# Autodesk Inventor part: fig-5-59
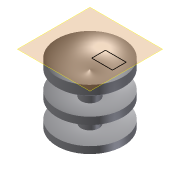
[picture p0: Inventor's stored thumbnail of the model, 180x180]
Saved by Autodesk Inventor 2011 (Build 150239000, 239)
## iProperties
Created: 2004-05
Part Number: fig-5-59
Document SubType Name: Modeling
Designer: CADCIM Technologies
Manufacturer: Standard
Standards Organization: Custom
Density: 1 g/cm^3
Author: CADCIM Technologies
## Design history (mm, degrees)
sketch "Sketch1"
  geometry: L1 (0.098, 22.743)-(0.098, 0.516); L2 (-3.621, 19.305)-(-3.621, 13.061); L3 (-3.621, 10.379)-(-3.621, 3.25); L4 (-3.664, 0.516)-(0.098, 0.516); L5 (-13.694, 4.7)-(-13.694, 1.836); L6 (-13.694, 26.851)-(-13.694, 23.014); L7 (-13.694, 15.335)-(-13.694, 12.343); A1 r 10.546 centre (-4.597, 32.185) between (-13.694, 26.851) and (0.098, 22.743); A2 r 21.828 centre (-4.597, 32.185) between (-13.694, 12.343) and (-3.621, 10.379); A3 r 12.918 centre (-4.597, 32.185) between (-13.694, 23.014) and (-3.621, 19.305); A4 r 19.149 centre (-4.597, 32.185) between (-13.694, 15.335) and (-3.621, 13.061); A5 r 28.952 centre (-4.597, 32.185) between (-13.694, 4.7) and (-3.621, 3.25); A6 r 31.683 centre (-4.597, 32.185) between (-13.694, 1.836) and (-3.664, 0.516)
  constraints: 14 end point, 12 point on circle, 6 centre point, 4 perpendicular, 2 parallel, 1 vertical
revolve "Revolution1" sketch "Sketch1" stored, may be unused: angle "d0" = 90 deg
workplane "Work Plane1"
sketch "Sketch2"
  geometry: L1 (3.408, -2.846)-(12.06, -2.846); L2 (12.06, -2.846)-(12.06, 2.873); L3 (12.06, 2.873)-(3.408, 2.873); L4 (3.408, 2.873)-(3.408, -2.846)
  constraints: 8 end point, 2 parallel, 1 horizontal, 1 perpendicular
body "Solid1"
